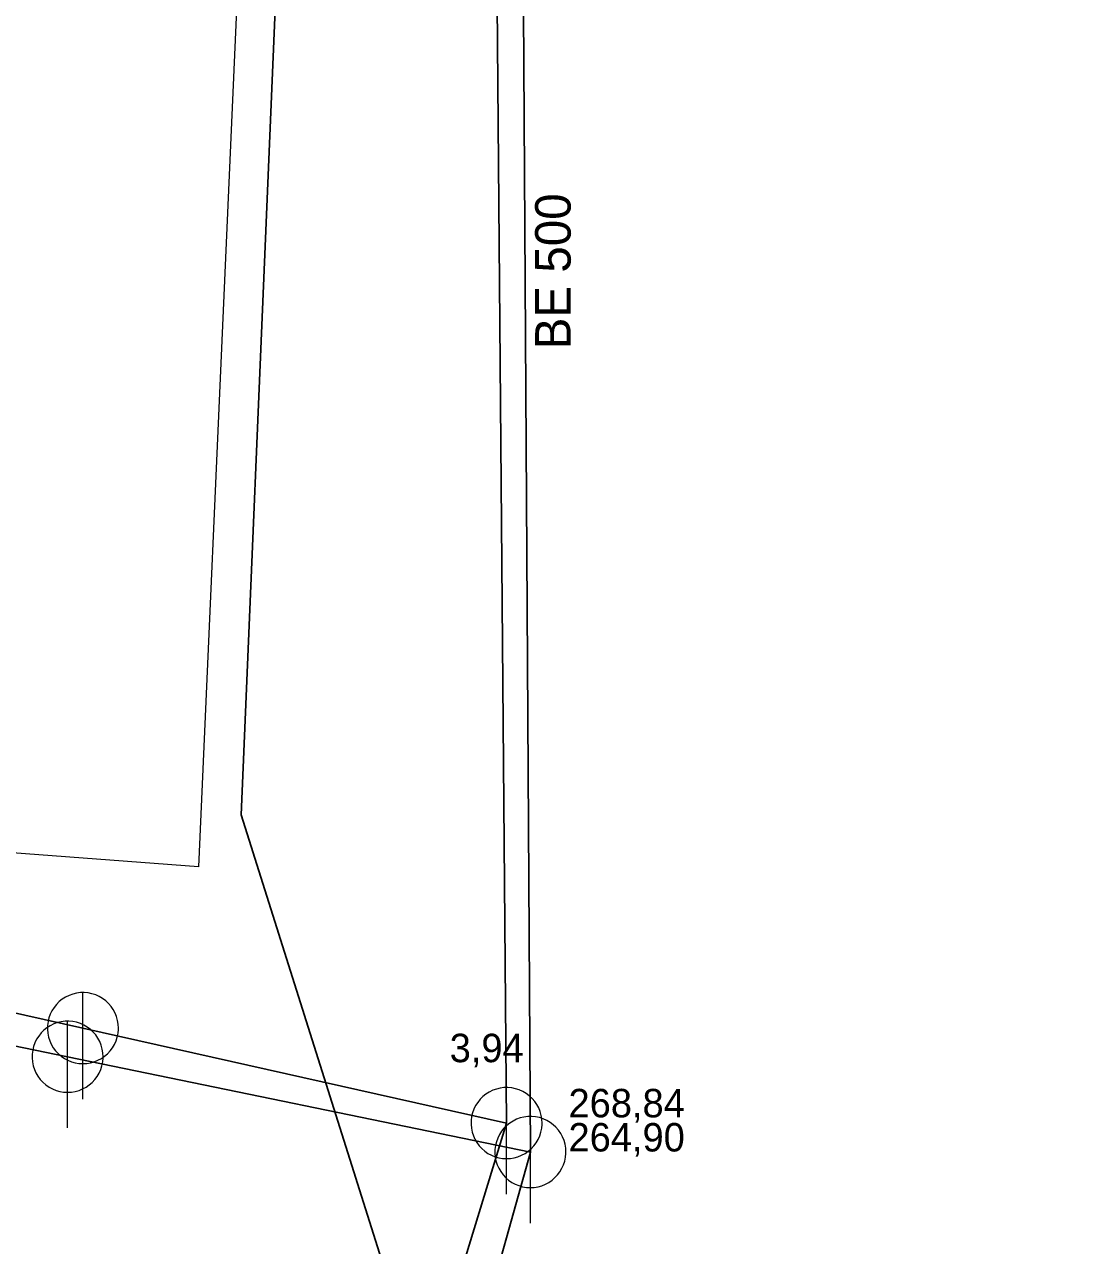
# Model space of a CAD drawing. Extents: x -725153 to -724843, y -978146 to -977794.
# Drawn here: x -724941.51 to -724911.38, y -978051.77 to -978017.43 of the extents above; entities that cross this region are included whole.
import ezdxf

# ---------------------------------------------------------------- set-up
doc = ezdxf.new("R2010")
doc.units = 0
doc.header["$LTSCALE"] = 0.32
doc.layers.add('1', color=7, linetype='Continuous')
for name, color, linetype, lineweight in [('13', 7, 'Continuous', 13), ('14', 7, 'Continuous', 25), ('17', 7, 'Continuous', 25), ('22', 7, 'Continuous', 13)]:
    doc.layers.add(name, color=color, linetype=linetype, lineweight=lineweight)

msp = doc.modelspace()

# ---------------------------------------------------------------- linework, layer by layer
at = {"layer": '13'}
msp.add_lwpolyline([(-724933.498, -977970.916), (-724936.609, -978041.12), (-724949.342, -978040.159)], dxfattribs=at)
at = {"layer": '14'}
for p, q in [((-724939.86, -978045.655), (-724927.944, -978048.326)), ((-724940.291, -978046.46), (-724927.274, -978049.14)), ((-724927.944, -978048.326), (-724943.585, -978099.465)), ((-724927.274, -978049.14), (-724941.044, -978098.504))]:
    msp.add_line(p, q, dxfattribs=at)
for points in [[(-724924.849, -977949.559), (-724927.569, -978000.189), (-724927.274, -978049.14)], [(-724926.682, -977953.405), (-724928.359, -977998.839), (-724927.944, -978048.326)], [(-724967.75, -978026.7), (-724965.91, -978041.188), (-724940.291, -978046.46)], [(-724965.475, -978027.672), (-724964.383, -978040.159), (-724939.86, -978045.655)]]:
    msp.add_lwpolyline(points, dxfattribs=at)
at = {"layer": '17'}
msp.add_lwpolyline([(-724911.375, -978083.783), (-724931.616, -978079.579), (-724929.686, -978057.78), (-724935.405, -978039.66), (-724932.296, -977965.921)], dxfattribs=at)
at = {"layer": '22'}
for p, q in [((-724939.86, -978047.655), (-724939.859, -978044.655)), ((-724940.291, -978048.46), (-724940.29, -978045.46)), ((-724927.944, -978050.326), (-724927.943, -978047.326)), ((-724927.274, -978051.14), (-724927.273, -978048.14))]:
    msp.add_line(p, q, dxfattribs=at)
for points in [[(-724938.86, -978045.655), (-724938.865, -978045.546), (-724938.883, -978045.438), (-724938.913, -978045.332), (-724938.953, -978045.231), (-724939.005, -978045.134), (-724939.067, -978045.044), (-724939.139, -978044.961), (-724939.219, -978044.887), (-724939.307, -978044.821), (-724939.401, -978044.766), (-724939.501, -978044.721), (-724939.606, -978044.688), (-724939.713, -978044.666), (-724939.822, -978044.656), (-724939.932, -978044.658), (-724940.04, -978044.672), (-724940.147, -978044.697), (-724940.25, -978044.734), (-724940.348, -978044.783), (-724940.44, -978044.841), (-724940.526, -978044.91), (-724940.603, -978044.987), (-724940.672, -978045.073), (-724940.731, -978045.165), (-724940.779, -978045.263), (-724940.816, -978045.366), (-724940.842, -978045.473), (-724940.856, -978045.581), (-724940.859, -978045.691), (-724940.849, -978045.8), (-724940.828, -978045.907), (-724940.794, -978046.011), (-724940.75, -978046.111), (-724940.695, -978046.206), (-724940.629, -978046.294), (-724940.555, -978046.374), (-724940.472, -978046.446), (-724940.382, -978046.508), (-724940.286, -978046.56), (-724940.184, -978046.601), (-724940.079, -978046.631), (-724939.971, -978046.649), (-724939.861, -978046.655), (-724939.752, -978046.649), (-724939.644, -978046.631), (-724939.539, -978046.602), (-724939.437, -978046.561), (-724939.34, -978046.509), (-724939.25, -978046.447), (-724939.167, -978046.376), (-724939.092, -978046.296), (-724939.027, -978046.208), (-724938.971, -978046.114), (-724938.927, -978046.014), (-724938.893, -978045.91), (-724938.871, -978045.802), (-724938.861, -978045.693)], [(-724939.291, -978046.46), (-724939.296, -978046.351), (-724939.314, -978046.243), (-724939.344, -978046.137), (-724939.384, -978046.036), (-724939.436, -978045.939), (-724939.498, -978045.849), (-724939.57, -978045.766), (-724939.65, -978045.692), (-724939.738, -978045.626), (-724939.832, -978045.571), (-724939.932, -978045.526), (-724940.037, -978045.493), (-724940.144, -978045.471), (-724940.253, -978045.461), (-724940.363, -978045.463), (-724940.471, -978045.477), (-724940.578, -978045.502), (-724940.681, -978045.539), (-724940.779, -978045.588), (-724940.871, -978045.646), (-724940.957, -978045.715), (-724941.034, -978045.792), (-724941.103, -978045.878), (-724941.162, -978045.97), (-724941.21, -978046.068), (-724941.247, -978046.171), (-724941.273, -978046.278), (-724941.287, -978046.386), (-724941.29, -978046.496), (-724941.28, -978046.605), (-724941.259, -978046.712), (-724941.225, -978046.816), (-724941.181, -978046.916), (-724941.126, -978047.011), (-724941.06, -978047.099), (-724940.986, -978047.179), (-724940.903, -978047.251), (-724940.813, -978047.313), (-724940.717, -978047.365), (-724940.615, -978047.406), (-724940.51, -978047.436), (-724940.402, -978047.454), (-724940.292, -978047.46), (-724940.183, -978047.454), (-724940.075, -978047.436), (-724939.97, -978047.407), (-724939.868, -978047.366), (-724939.771, -978047.314), (-724939.681, -978047.252), (-724939.598, -978047.181), (-724939.523, -978047.101), (-724939.458, -978047.013), (-724939.402, -978046.919), (-724939.358, -978046.819), (-724939.324, -978046.715), (-724939.302, -978046.607), (-724939.292, -978046.498)], [(-724926.944, -978048.326), (-724926.949, -978048.217), (-724926.967, -978048.109), (-724926.997, -978048.003), (-724927.037, -978047.902), (-724927.089, -978047.805), (-724927.151, -978047.715), (-724927.223, -978047.632), (-724927.303, -978047.558), (-724927.391, -978047.492), (-724927.485, -978047.437), (-724927.585, -978047.392), (-724927.69, -978047.359), (-724927.797, -978047.337), (-724927.906, -978047.327), (-724928.016, -978047.329), (-724928.124, -978047.343), (-724928.231, -978047.368), (-724928.334, -978047.405), (-724928.432, -978047.454), (-724928.524, -978047.512), (-724928.61, -978047.581), (-724928.687, -978047.658), (-724928.756, -978047.744), (-724928.815, -978047.836), (-724928.863, -978047.934), (-724928.9, -978048.037), (-724928.926, -978048.144), (-724928.94, -978048.252), (-724928.943, -978048.362), (-724928.933, -978048.471), (-724928.912, -978048.578), (-724928.878, -978048.682), (-724928.834, -978048.782), (-724928.779, -978048.877), (-724928.713, -978048.965), (-724928.639, -978049.045), (-724928.556, -978049.117), (-724928.466, -978049.179), (-724928.37, -978049.231), (-724928.268, -978049.272), (-724928.163, -978049.302), (-724928.055, -978049.32), (-724927.945, -978049.326), (-724927.836, -978049.32), (-724927.728, -978049.302), (-724927.623, -978049.273), (-724927.521, -978049.232), (-724927.424, -978049.18), (-724927.334, -978049.118), (-724927.251, -978049.047), (-724927.176, -978048.967), (-724927.111, -978048.879), (-724927.055, -978048.785), (-724927.011, -978048.685), (-724926.977, -978048.581), (-724926.955, -978048.473), (-724926.945, -978048.364)], [(-724926.274, -978049.14), (-724926.279, -978049.031), (-724926.297, -978048.923), (-724926.327, -978048.817), (-724926.367, -978048.716), (-724926.419, -978048.619), (-724926.481, -978048.529), (-724926.553, -978048.446), (-724926.633, -978048.372), (-724926.721, -978048.306), (-724926.815, -978048.251), (-724926.915, -978048.206), (-724927.02, -978048.173), (-724927.127, -978048.151), (-724927.236, -978048.141), (-724927.346, -978048.143), (-724927.454, -978048.157), (-724927.561, -978048.182), (-724927.664, -978048.219), (-724927.762, -978048.268), (-724927.854, -978048.326), (-724927.94, -978048.395), (-724928.017, -978048.472), (-724928.086, -978048.558), (-724928.145, -978048.65), (-724928.193, -978048.748), (-724928.23, -978048.851), (-724928.256, -978048.958), (-724928.27, -978049.066), (-724928.273, -978049.176), (-724928.263, -978049.285), (-724928.242, -978049.392), (-724928.208, -978049.496), (-724928.164, -978049.596), (-724928.109, -978049.691), (-724928.043, -978049.779), (-724927.969, -978049.859), (-724927.886, -978049.931), (-724927.796, -978049.993), (-724927.7, -978050.045), (-724927.598, -978050.086), (-724927.493, -978050.116), (-724927.385, -978050.134), (-724927.275, -978050.14), (-724927.166, -978050.134), (-724927.058, -978050.116), (-724926.953, -978050.087), (-724926.851, -978050.046), (-724926.754, -978049.994), (-724926.664, -978049.932), (-724926.581, -978049.861), (-724926.506, -978049.781), (-724926.441, -978049.693), (-724926.385, -978049.599), (-724926.341, -978049.499), (-724926.307, -978049.395), (-724926.285, -978049.287), (-724926.275, -978049.178)]]:
    msp.add_lwpolyline(points, close=True, dxfattribs=at)

# ---------------------------------------------------------------- texts
at = {"layer": '1'}
msp.add_text('BE 500', height=1, rotation=90, dxfattribs=at).set_placement((-724926.14, -978026.565))
msp.add_text('3,94', height=0.8, dxfattribs=at).set_placement((-724929.543, -978046.614))
at = {"layer": '22'}
for s, p in [('268,84', (-724926.201, -978048.165)), ('264,90', (-724926.201, -978049.125))]:
    msp.add_text(s, height=0.8, dxfattribs=at).set_placement(p)

doc.saveas('drawing.dxf')
